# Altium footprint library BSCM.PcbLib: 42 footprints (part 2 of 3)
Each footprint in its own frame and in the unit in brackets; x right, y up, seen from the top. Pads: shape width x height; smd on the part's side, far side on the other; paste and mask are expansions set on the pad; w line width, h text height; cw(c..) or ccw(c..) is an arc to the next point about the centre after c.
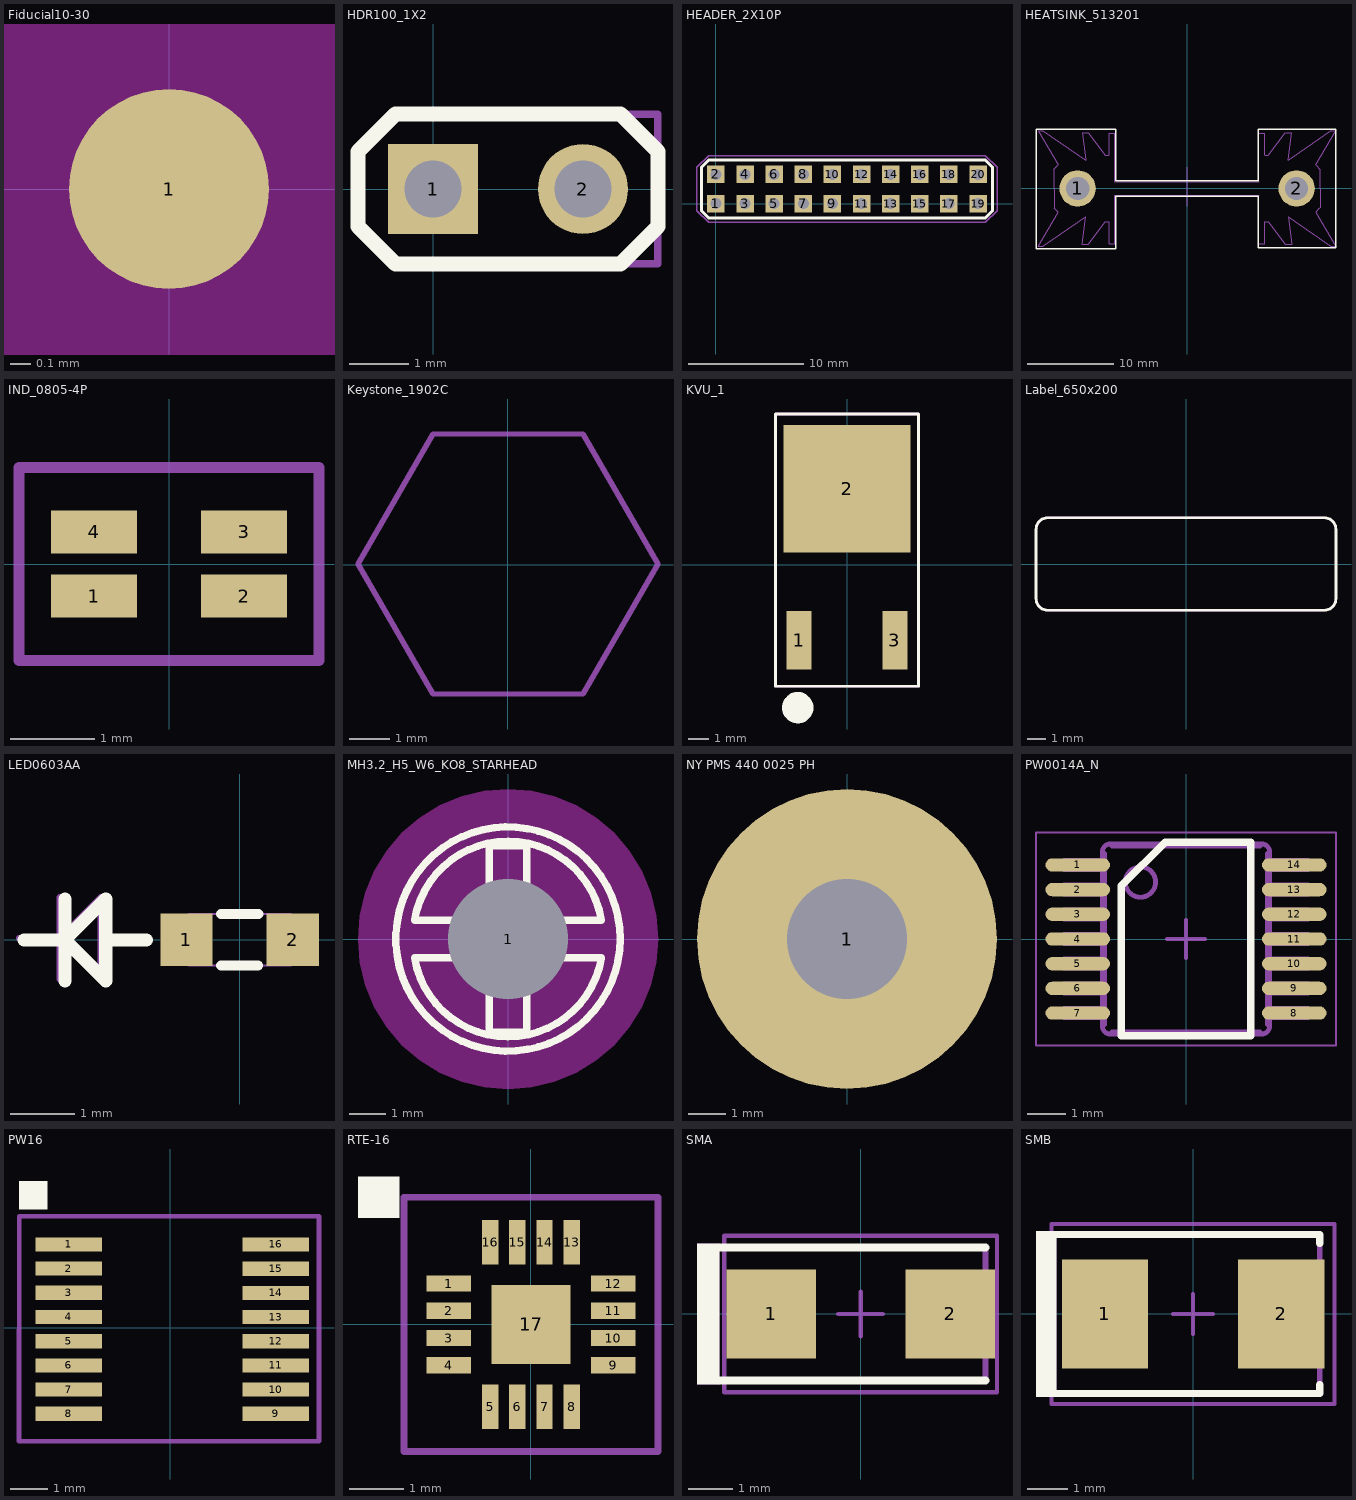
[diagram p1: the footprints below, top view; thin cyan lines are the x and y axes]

## Fiducial10-30 [mm]
pads (1):
  round 1 smd mask+1: 1(0,0)
Top Layer keep-out:
  circle w1.678: c0,0 r0.75

## HDR100_1X2 [mil]
pads (2):
  rect 60x60 hole 38: 1(0,0)
  round 60 hole 38: 2(100,0)
Top Overlay:
  lines w10: -50,-25 -50,25 -25,50 125,50 150,25 150,-25 125,-50 -25,-50 -50,-25
Mechanical 5:
  lines w5: -50,-25 -25,-50 150,-50 150,50 -25,50 -50,25 -50,-25
  text ".Designator" at 97,-69 h40

## HEADER_2X10P [mil]
pads (20):
  rect 60x60 hole 38: 1(0,0) 2(0,100) 3(100,0) 4(100,100) 5(200,0) 6(200,100) 7(300,0) 8(300,100) 9(400,0) 10(400,100) 11(500,0) 12(500,100) 13(600,0) 14(600,100) 15(700,0) 16(700,100) 17(800,0) 18(800,100) 19(900,0) 20(900,100)
Top Overlay:
  lines w10: -50,-25 -50,125 -25,150 925,150 950,125 950,-25 925,-50 -25,-50 -50,-25
Mechanical 5:
  lines w5: -65,-25 -65,125 -25,165 925,165 965,125 965,-25 925,-65 -25,-65 -65,-25
  text ".Designator" at 485.01,71.01 h40
  text "*" at -44,-41 h40

## HEATSINK_513201 [mil]
pads (2):
  round 166 hole 106.5: 1(-500,0) 2(500,0)
Top Overlay:
  lines w6: -690,-275 -325,-275 -325,-35 325,-35 325,-255 325,-270 680,-270 680,270 325,270 325,265 325,35 315,35 -305,35 -325,35 -325,240 -325,270 -690,270 -690,-275
Mechanical 5:
  lines w5: -680,-263 -589,-108 ; -679,-264 -657,-264 ; -659,-264 -463,-129 ; -608,-87 -591,-107 ; -608,86 -607,-88 ; -608,87 -591,107 ; -589,108 -680,263 -659,264 -463,129 ; -463,-130 -479,-254 -452,-254 ; -463,130 -479,254 -452,254 ; -451,-254 -373,-152 -358,-152 ; -451,254 -373,152 -358,152 ; -356,-152 -356,-252 -331,-252 ; -356,152 -356,252 -331,252 ; -330,-250 -330,-31 330,-31 ; -330,250 -330,31 330,31 ; 1,-82 1,96 ; 328,-250 328,-31 ; 328,31 328,250 ; 329,-252 354,-252 354,-152 ; 329,252 354,252 354,152 ; 356,-152 371,-152 449,-254 ; 356,152 371,152 449,254 ; 450,-254 477,-254 461,-130 ; 450,254 477,254 461,130 ; 461,-129 657,-264 ; 461,129 657,264 ; 587,-108 678,-263 ; 587,108 678,263 ; 589,-107 606,-87 ; 589,107 606,87 607,-87 ; 655,-264 677,-264 ; 655,264 677,264
  text ".Designator" at 39,145 h40

## IND_0805-4P [mil]
pads (4):
  rect 40x20 smd: 1(-35,-15) 2(35,-15) 3(35,15) 4(-35,15)
Mechanical 5:
  lines w5: -70,-45 -70,45 70,45 70,-45 -70,-45
  text "*" at -72.86,-84.35 h40
  text ".Designator" at -25,-17 h40

## Keystone_1902C [mil] "Hex Standoff, 4-40 threaded, nylon"
height 500
Mechanical 5:
  lines w5: -145.29,0.49 -72.56,126.47 72.92,126.47 145.65,0.49 72.92,-125.49 -72.56,-125.49 -145.29,0.49
3D body: height 501, standoff 1, extent -144.95,-125.98 146,125.98

## KVU_1 [mm]
height 2.39
pads (3):
  rect 1.2x2.8 smd: 1(-2.29,-3.635) 3(2.29,-3.635)
  rect 6.096x6.096 smd: 2(0,3.635)
Top Overlay:
  circle w0.889: c-2.362,-6.858 r0.305
  lines w0.127: -3.429,-5.841 -3.429,7.216 3.429,7.216 3.429,-5.841 -3.429,-5.841
Mechanical 5:
  lines w0.127: -3.429,-5.841 3.429,-5.841 3.429,7.216 -3.429,7.216 -3.429,-5.841
  text ".Designator" at 0.838,0.381 h1.02

## Label_650x200 [mil] "Thermal Transfer Label"
height 1
Top Overlay:
  lines w6: -325,-75 ccw(c-300,-75) -300,-100 300,-100 ccw(c300,-75) 325,-75 325,75 ccw(c300,75) 300,100 -300,100 ccw(c-300,75) -325,75 -325,-75
Mechanical 5:
  lines w5: -325,-75 ccw(c-300,-75) -300,-100 300,-100 ccw(c300,-75) 325,-75 325,75 ccw(c300,75) 300,100 -300,100 ccw(c-300,75) -325,75 -325,-75
  text ".Designator" at -60,-20 h36
3D body: height 1, standoff 0, extent -325.51,-100.51 325.51,100.51

## LED0603AA [mil]
height 35.43
pads (2):
  rect 32x32 smd: 1(-32.48,0) 2(32.48,0)
Top Overlay:
  lines w6: -11.42,-15.75 11.42,-15.75 ; -11.42,15.75 11.42,15.75
  lines w8: -131.79,-0.04 -106.79,-0.04 ; -106.79,-25.04 -106.79,24.96 ; -81.79,-0.04 -56.79,-0.04 ; -106.79,-0.04 -81.79,-25.04 -81.79,24.96 -106.79,-0.04
Mechanical 15:
  lines w1: -31.5,-15.75 -31.5,15.75 31.5,15.75 31.5,-15.75 -31.5,-15.75
  lines w3.94: -134.79,0.96 -109.79,0.96 ; -109.79,-24.04 -109.79,25.96 ; -84.79,0.96 -59.79,0.96 ; -109.79,0.96 -84.79,-24.04 -84.79,25.96 -109.79,0.96

## MH3.2_H5_W6_KO8_STARHEAD [mil]
height 80
pads (1):
  round 20 / inner round 142 / far side round 20 hole 128 unplated mask+64: 1(0,0)
Top Overlay:
  circle w8: c0,0 r120
  lines w8: -100,-20 -20,-20 -20,-100 20,-100 20,-20 100,-20 ; -100.02,-19.91 ccw(c0,-3.35) 99.99,-20.08 ; -100,20 -20,20 -20,100 20,100 20,20 100,20 ; -99.99,20.09 cw(c0,3.36) 100.02,19.92
Keep-Out Layer:
  region: 160.49,0 158.52,25.11 152.64,49.6 143,72.86 129.84,94.34 113.49,113.49 94.34,129.84 72.86,143 49.6,152.64 25.11,158.52 0,160.49 -25.11,158.52 -49.6,152.64 -72.86,143 -94.34,129.84 -113.49,113.49 -129.84,94.34 -143,72.86 -152.64,49.6 -158.52,25.11 -160.49,0 -158.52,-25.11 -152.64,-49.6 -143,-72.86 -129.84,-94.34 -113.49,-113.49 -94.34,-129.84 -72.86,-143 -49.6,-152.64 -25.11,-158.52 0,-160.49 25.11,-158.52 49.6,-152.64 72.86,-143 94.34,-129.84 113.49,-113.49 129.84,-94.34 143,-72.86 152.64,-49.6 158.52,-25.11

## NY PMS 440 0025 PH [mm] "4-40 nylon screw and mounting hole"
height 1.905
pads (1):
  round 8 hole 3.2: 1(0,0)
Mechanical 5:
  circle w0.127: c0,0 r3.789
  text ".Designator" at -1.524,-0.508 h1.02
3D body: height 2.69, standoff -8.74, extent -3.302,-3.3 3.296,3.3

## PW0014A_N [mm] "TSOP, 14-Leads, Body 5x4.4mm, Pitch 0.65mm, IPC Medium Density"
height 1.2
pads (14):
  oval 1.7x0.35 smd: 1(-2.85,1.95) 2(-2.85,1.3) 3(-2.85,0.65) 4(-2.85,0) 5(-2.85,-0.65) 6(-2.85,-1.3) 7(-2.85,-1.95) 8(2.85,-1.95) 9(2.85,-1.3) 10(2.85,-0.65) 11(2.85,0) 12(2.85,0.65) 13(2.85,1.3) 14(2.85,1.95)
Top Overlay:
  lines w0.2: -1.7,-2.55 1.7,-2.55 1.7,2.55 -0.55,2.55 -1.7,1.4 -1.7,-2.55
Mechanical 5:
  drawing of 182 lines, arcs and shapes, not listed
  text ".Designator" at 0.693,-0.903 h1.02
Mechanical 15:
  lines w0.05: -3.95,-2.8 -3.95,2.8 3.95,2.8 3.95,-2.8 -3.95,-2.8
  lines w0.1: -0.5,0 0.5,0 ; 0,-0.5 0,0.5
3D body: height 0.98, standoff -0.02, extent -3.21,-2.5 3.21,2.5

## PW16 [mil]
pads (16):
  rect 70x15 smd: 1(-107.3,88) 2(-107.3,62.4) 3(-107.3,36.8) 4(-107.3,11.2) 5(-107.3,-14.4) 6(-107.3,-40) 7(-107.3,-65.6) 8(-107.3,-91.2) 9(111.7,-91.3) 10(111.7,-65.7) 11(111.7,-40.1) 12(111.7,-14.5) 13(111.7,11.1) 14(111.7,36.7) 15(111.7,62.3) 16(111.7,88)
Top Overlay:
  region: -160,125 -130,125 -130,155 -160,155
Mechanical 5:
  lines w5: 157.4,-120.4 -159.9,-120.4 -159.84,117.72 157.48,117.91 ; 157.4,-120.3 157.4,117.9
  text "*" at -63.6,48.5 h30
  text ".Designator" at -60,-20 h40

## RTE-16 [mil]
pads (17):
  rect 32.24x11.8 smd: 1(-59.45,29.55) 2(-59.45,9.85) 3(-59.45,-9.85) 4(-59.45,-29.55) 9(59.55,-29.55) 10(59.55,-9.85) 11(59.55,9.85) 12(59.55,29.55)
  rect 11.8x32.24 smd: 5(-29.5,-59.5) 6(-9.8,-59.5) 7(9.9,-59.5) 8(29.6,-59.5) 14(9.9,59.5) 15(-9.8,59.5) 16(-29.5,59.5)
  rect 11.8x32.24 smd mask+2: 13(29.6,59.5)
  rect 57.09x57.09 smd: 17(0.15,-0.05)
Top Overlay:
  region: -125.15,77.05 -95.15,77.05 -95.15,107.05 -125.15,107.05
Mechanical 5:
  lines w5: -92,-92 92,-92 92,92 -92,92 -92,-92
  text "*" at -82.15,23.05 h40
  text ".Designator" at -19.15,34.05 h40

## SMA [mm] "Molded Diode, 2-Leads, Body 4.3x2.6mm, IPC Medium Density, based on OnSemi component dimensions and land pattern"
height 2.27
pads (2):
  rect 2x2 smd: 1(-2,0) 2(2,0)
Top Overlay:
  rectangle: -3.658,-1.575 -3.15,1.575
  lines w0.178: -3.327,-1.486 2.794,-1.486 ; -3.327,1.486 2.794,1.486
Mechanical 5:
  rectangle: -3.658,-1.575 -3.15,1.575
  lines w0.127: -3.327,-1.486 2.794,-1.486 2.794,1.486 -3.327,1.486
  text ".Designator" at 0.711,0.432 h1.02
Mechanical 15:
  lines w0.1: -0.5,0 0.5,0 ; 0,-0.5 0,0.5 ; -3.05,-1.75 3.05,-1.75 3.05,1.75 -3.05,1.75 -3.05,-1.75
3D body: height 2.42, standoff 0.02, extent -2.6,-1.3 2.6,1.3

## SMB [mil] "Molded Diode, 2-Leads, Body 5.4x3.6mm, IPC Medium Density, based on OnSemi component dimensions"
height 96.46
pads (2):
  rect 85x107.99 smd: 1(-87.01,0) 2(87.01,0)
Top Overlay:
  rectangle: -155,-82 -135,82
  lines w7: -142,-78.5 125,-78.5 125,-69.5 ; -142,78.5 125,78.5 125,69.5
Mechanical 5:
  rectangle: -155,-82 -135,82
  lines w5: -142,-78.5 125,-78.5 125,-69.5 125,69.5 125,78.5 -142,78.5
  text ".Designator" at 28,19 h40
Mechanical 15:
  lines w3.94: -19.68,0 19.69,0 ; 0,-19.69 0,19.68 ; -139.76,-88.58 -139.76,88.58 139.76,88.58 139.76,-88.58 -139.76,-88.58
3D body: height 91.35, standoff 0.6, extent -106.3,-70.86 106.3,70.87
